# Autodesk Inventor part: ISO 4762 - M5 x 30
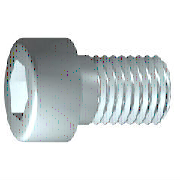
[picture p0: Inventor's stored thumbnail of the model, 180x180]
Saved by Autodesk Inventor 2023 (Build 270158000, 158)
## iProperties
Created: 2015-02
Part Number: ISO 4762 - M5 x 30
Material: Stainless Steel, 440C
Description: Hexagon Socket Head Cap Screw
Document SubType Name: Modeling
Standard: ISO 4762
Designer: Cadskolen
Standard Revision: Fourth edition 2004-03-01
Standards Organization: ISO
Language: en-US
Size Designation: M5 x 30
Categories: <MemberInstance><Categories><Category DisplayName="Fasteners" InternalName="e4da775c-781d-43d5-af7c-5136215cf5a6" Mnemonic="FSTN"><Category DisplayName="Bolts"
Density: 7.75 g/cm^3
Appearance: Semi-Polished
Mass: 6.41515 g
Surface Area: 7.45317 cm^2
Volume: 0.827761 cm^3
IsCustomPart: 0
Author: Cadskolen
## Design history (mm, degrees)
sketch "Sketch1"
  geometry: L1 (-1.167, 0)-(30, 0); L2 (30, 0)-(30, 2.5); L3 (30, 2.5)-(8, 2.5); L4 (8, 2.5)-(7.509, 2.5); L5 (7.509, 2.5)-(0, 2.5); L6 (0, 2.5)-(0, 4.25); L7 (0, 4.25)-(-5, 4.25); L8 (-5, 4.25)-(-5, 2.309); L9 (-5, 2.309)-(-2.5, 2.309); L10 (-2.5, 2.309)-(-1.167, 0); L11 (-12, 0)-(37, 0) reference; L12 (0, -0.85)-(0, 5.1) reference; L13 (8, 2.5)-(0, 2.5)
  constraints: 22 end point, 6 parallel, 2 collinear, 2 perpendicular, 1 horizontal, 1 point on line
  dimensions: "d1" = 22 distance from line of L3.end L2 (= GEL); "d2" = 0.49086 distance of L4.end L3.end (computed from GAL); "d3" = 5 distance between parallel lines of L8 L6 (= KOH); "d4" = 2.5 distance of L8.end L9.end (= INTI); "d5" = 60 deg angle of L10 L1; "d6" = 5 diameter of L3 L1 (= GD); "d7" = 5 diameter of L5 L1 (= BDM); "d8" = 4.6188 diameter of L9 L1 (= 1.1547 x SW); "d9" = 8.5 diameter of L7 L1 (= KOD); "d26" = 30 distance between parallel lines of L12 L2 (= NLG)
revolve "Body" sketch "Sketch1" stored, may be unused: angle "d10" = 90 deg
sketch "Sketch2"
  geometry: L1 (0, -5.95)-(0, 5.95) reference; L2 (-5.95, 0)-(5.95, 0) reference; L3 (2.309, 0)-(1.155, -2); L4 (1.155, -2)-(-1.155, -2); L5 (-1.155, -2)-(-2.309, 0); L6 (-2.309, 0)-(-1.155, 2); L7 (-1.155, 2)-(1.155, 2); L8 (1.155, 2)-(2.309, 0); 2 further points
  constraints: 12 end point, 1 coincident, 1 horizontal alignment, 1 point on line, 12 other
extrude "Slot" join sketch "Sketch2" stored distance "d11" = 10; taper "d12" = 0 deg
workplane "Work Plane1"
fillet "Fillet2" dims "d30" = 0.1 (= R)
body "Solid1"
fillet "Fillet1" dims "d17" = 0.5 (= RR)
feature "Thread" dims "d13" = 22 (= GEL), "d14" = 0
chamfer "Chamfer1" distance "d15" = 0.49076 (= -0.5 x SPD + 0.5 x GD); stored, may be unused: second distance "d16" = 0.49076 (= GUL), angle "d27" = 45 deg
other parameters: "GD" = 5 [user parameter; used in 2 equation terms], "NLG" = 30 [user parameter; used in 1 equation term], "GEL" = 22 [user parameter; used in 2 equation terms], "KOD" = 8.5 [user parameter; used in 1 equation term], "KOH" = 5 [user parameter; used in 1 equation term], "INTI" = 2.5 [user parameter; used in 1 equation term], "GAL" = 0.49076 (= 0.61345 x PTC) [user parameter; used in 1 equation term], "GUL" = 0.49076 (= 0.61345 x PTC) [user parameter; used in 1 equation term], "BDM" = 5 (= NND) [user parameter; used in 1 equation term], "SW" = 4 [user parameter; used in 2 equation terms], "RR" = 0.5 [user parameter; used in 1 equation term], "SPD" = 4.01848 (= NND - 1.2269 x PTC) [user parameter; used in 1 equation term], "d19" = 0, "d28" = 0, "d29" = 0, "R" = 0.1 [user parameter; used in 1 equation term], "TOA" = 30 deg [user parameter], "GD1" = 4.01848 (= THREADDIA - 1.2269 x PTC) [user parameter], "THREADDIA" = 5 [user parameter; used in 1 equation term], "FAWI" = 45 deg [user parameter], "TPU" = 12.5 (computed from PTC) [user parameter], "PTC" = 0.8 [user parameter; used in 5 equation terms], "NND" = 5 [user parameter; used in 2 equation terms], "E0" = 4.62 (= 1.155 x SW) [user parameter]
